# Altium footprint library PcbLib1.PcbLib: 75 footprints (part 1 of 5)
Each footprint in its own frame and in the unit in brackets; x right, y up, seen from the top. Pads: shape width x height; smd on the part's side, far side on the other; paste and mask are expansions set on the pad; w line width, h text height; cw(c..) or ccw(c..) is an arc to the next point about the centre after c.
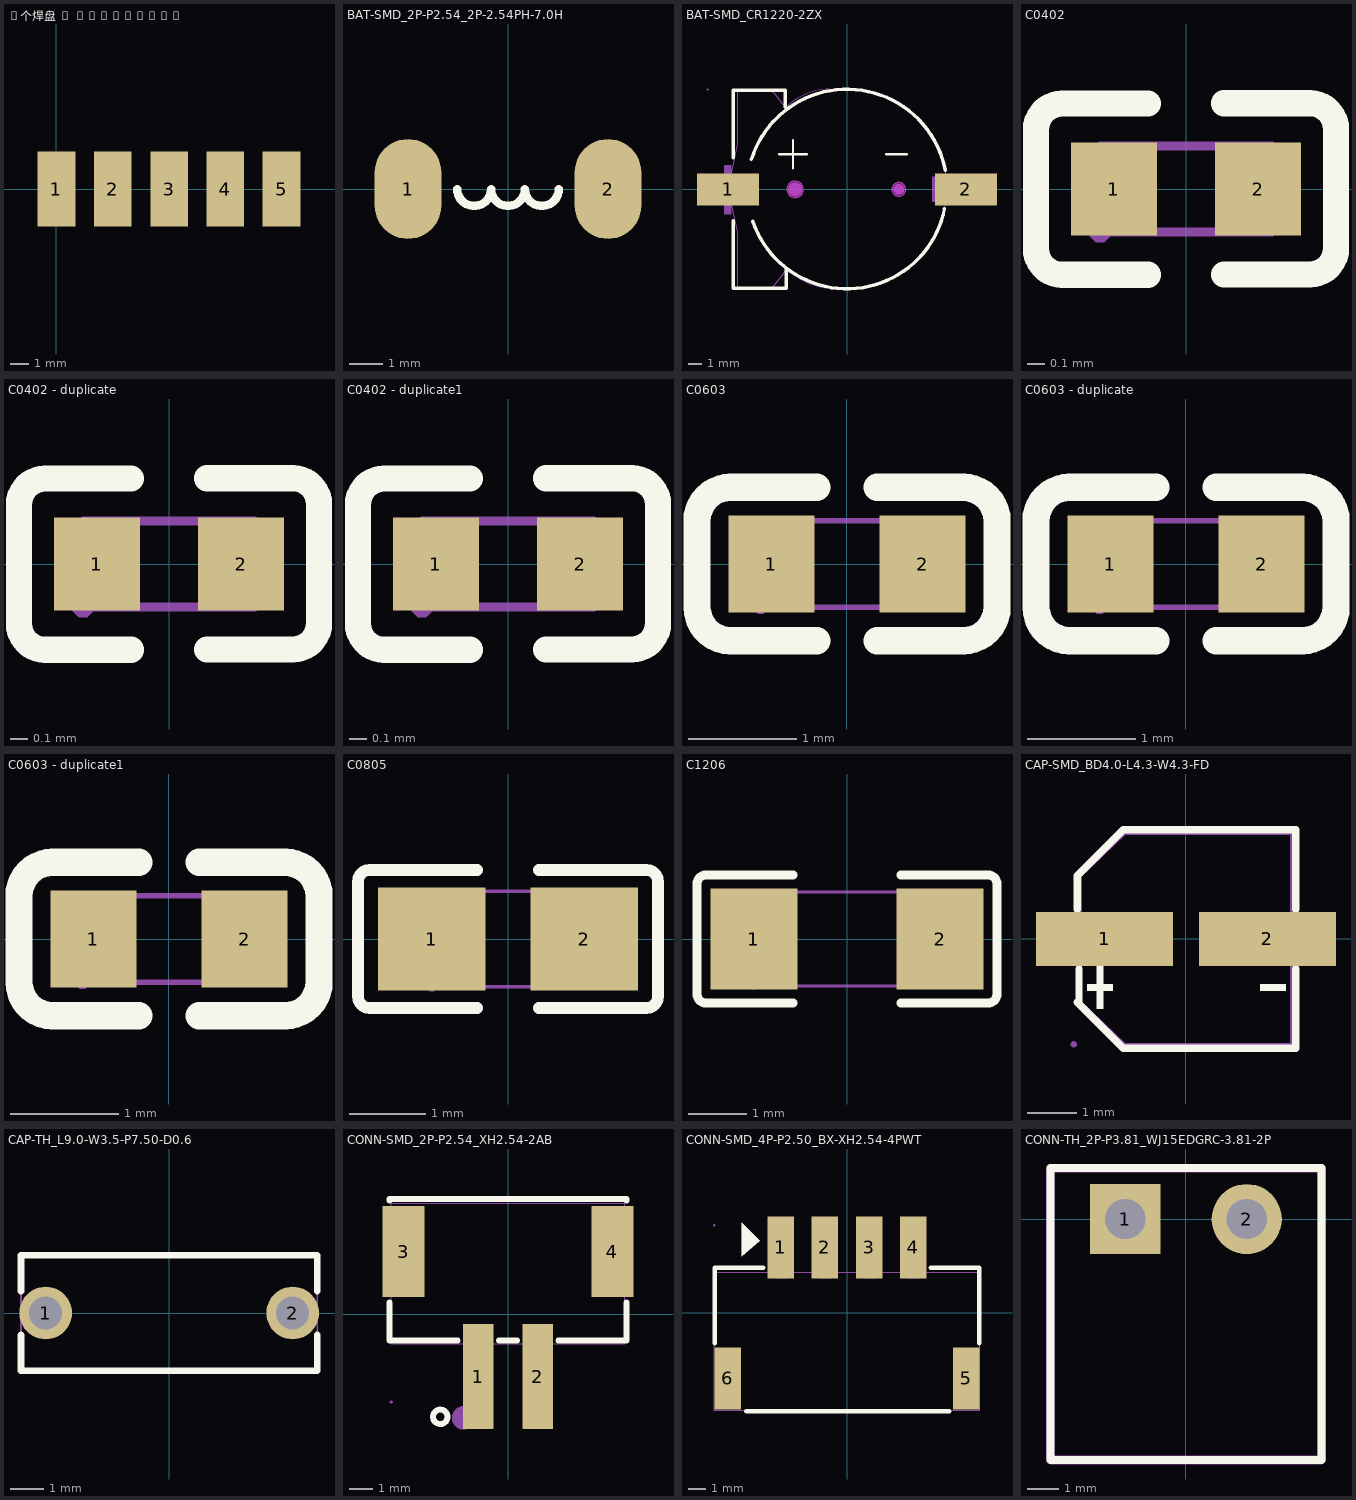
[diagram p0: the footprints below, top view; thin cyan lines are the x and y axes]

## 5个焊盘 - duplicate [mm]
pads (5):
  rect 2x4 smd: 1(0,0) 2(3,0) 3(6.001,0) 4(9,0) 5(12,0)

## BAT-SMD_2P-P2.54_2P-2.54PH-7.0H [mm]
pads (2):
  oval 2x3 smd paste+0 mask+0.05: 1(-3,0) 2(3,0)
Top Overlay:
  lines w0.254: -1.524,0 ccw(c-1.016,0) -0.508,0 ccw(c0,0) 0.508,0 ccw(c1.016,0) 1.524,0

## BAT-SMD_CR1220-2ZX [mm]
pads (2):
  rect 4.5x2.3 smd: 1(-8.6,0) 2(8.6,0)
Top Overlay:
  lines w0.152: -4.928,2.54 -2.896,2.54 ; -3.912,1.524 -3.912,3.556 ; 2.819,2.54 4.343,2.54
  lines w0.254: -8.24,-2.26 -8.24,-7.15 -4.4,-7.15 -4.4,-5.706 -4.378,-5.706 ; -8.24,2.3 -8.24,7.17 -5.51,7.17 -4.47,7.17 -4.47,5.95 ; -6.911,2.175 cw(c0,0) 7.109,1.399 ; -6.815,-2.297 ccw(c0,0) 7.051,-1.418
Keep-Out Layer:
  board cut-out: 4.25,0 4.25,-0.099 4.174,-0.283 4.033,-0.424 3.85,-0.5 3.651,-0.5 3.467,-0.424 3.326,-0.283 3.25,-0.099 3.25,0 3.25,0.099 3.326,0.283 3.467,0.424 3.651,0.5 3.85,0.5 4.033,0.424 4.174,0.283 4.25,0.099 4.25,0
  board cut-out: -3.15,0 -3.15,-0.119 -3.241,-0.34 -3.41,-0.509 -3.631,-0.6 -3.869,-0.6 -4.09,-0.509 -4.259,-0.34 -4.35,-0.119 -4.35,0 -4.35,0.119 -4.259,0.34 -4.09,0.509 -3.869,0.6 -3.631,0.6 -3.41,0.509 -3.241,0.34 -3.15,0.119 -3.15,0
Keep-Out Layer:
  circle w0.003: c3.75,0 r0.5
  circle w0.003: c-3.75,0 r0.6
  region: 4.25,0 4.25,-0.099 4.174,-0.283 4.033,-0.424 3.85,-0.5 3.651,-0.5 3.467,-0.424 3.326,-0.283 3.25,-0.099 3.25,0 3.25,0.099 3.326,0.283 3.467,0.424 3.651,0.5 3.85,0.5 4.033,0.424 4.174,0.283 4.25,0.099 4.25,0
  region: 4.25,0 4.24,-0.098 4.212,-0.191 4.166,-0.278 4.104,-0.354 4.028,-0.416 3.941,-0.462 3.848,-0.49 3.75,-0.5 3.653,-0.49 3.559,-0.462 3.472,-0.416 3.397,-0.354 3.334,-0.278 3.288,-0.191 3.26,-0.098 3.25,0 3.26,0.098 3.288,0.191 3.334,0.278 3.397,0.354 3.472,0.416 3.559,0.462 3.653,0.49 3.75,0.5 3.848,0.49 3.941,0.462 4.028,0.416 4.104,0.354 4.166,0.278 4.212,0.191 4.24,0.098
  region: -3.15,0 -3.15,-0.119 -3.241,-0.34 -3.41,-0.509 -3.631,-0.6 -3.869,-0.6 -4.09,-0.509 -4.259,-0.34 -4.35,-0.119 -4.35,0 -4.35,0.119 -4.259,0.34 -4.09,0.509 -3.869,0.6 -3.631,0.6 -3.41,0.509 -3.241,0.34 -3.15,0.119 -3.15,0
  region: -3.15,0 -3.159,-0.104 -3.186,-0.205 -3.23,-0.3 -3.29,-0.386 -3.364,-0.46 -3.45,-0.52 -3.545,-0.564 -3.646,-0.591 -3.75,-0.6 -3.854,-0.591 -3.955,-0.564 -4.05,-0.52 -4.136,-0.46 -4.21,-0.386 -4.27,-0.3 -4.314,-0.205 -4.341,-0.104 -4.35,0 -4.341,0.104 -4.314,0.205 -4.27,0.3 -4.21,0.386 -4.136,0.46 -4.05,0.52 -3.955,0.564 -3.854,0.591 -3.75,0.6 -3.646,0.591 -3.545,0.564 -3.45,0.52 -3.364,0.46 -3.29,0.386 -3.23,0.3 -3.186,0.205 -3.159,0.104
Mechanical 1:
  circle w0.003: c3.75,0 r0.5
  circle w0.003: c-3.75,0 r0.6
Mechanical 2:
  drawing of 9 lines, arcs and shapes, not listed
Mechanical 6:
  lines w0.051: -8.382,-1.016 -8.382,1.016 -7.89,3.3 -7.89,7.15 -5.47,7.15 -5.2,6.88 -4.47,5.92 -4.43,5.92 cw(c-1.232,2.722) -1.232,7.245 0.081,7.245 cw(c0.081,0.08) 7.245,0.08 7.245,0 cw(c0.053,0) 0.053,-7.192 0,-7.192 -0.843,-7.192 cw(c-0.843,-2.281) -4.315,-5.754 -5.26,-6.93 -5.48,-7.15 -7.89,-7.15 -7.89,-3.3 -8.38,-1.07 -8.382,-1.016
Mechanical 8:
  region: -10.01,7.215 -10.01,7.19 -10.045,7.155 -10.095,7.155 -10.13,7.19 -10.13,7.215 -10.13,7.24 -10.095,7.275 -10.045,7.275 -10.01,7.24 -10.01,7.215
Mechanical 9:
  region: -6.57,-0.9 -10.07,-0.9 -10.07,0.9 -6.57,0.9
  region: 6.17,0.9 9.67,0.9 9.67,-0.9 6.17,-0.9

## C0402 [mm]
pads (2):
  rect 0.5x0.54 smd: 1(-0.42,0) 2(0.42,0)
Top Overlay:
  lines w0.152: -0.221,-0.5 -0.721,-0.5 cw(c-0.721,-0.347) -0.874,-0.347 -0.874,0.345 cw(c-0.721,0.345) -0.721,0.498 -0.221,0.498 ; 0.221,-0.498 0.721,-0.498 ccw(c0.721,-0.345) 0.874,-0.345 0.874,0.347 ccw(c0.721,0.347) 0.721,0.5 0.221,0.5
Mechanical 6:
  lines w0.051: -0.5,-0.25 0.5,-0.25 0.5,0.25 -0.5,0.25 -0.5,-0.25
Mechanical 8:
  region: -0.44,-0.25 -0.44,-0.275 -0.475,-0.31 -0.525,-0.31 -0.56,-0.275 -0.56,-0.25 -0.56,-0.225 -0.525,-0.19 -0.475,-0.19 -0.44,-0.225 -0.44,-0.25
Mechanical 9:
  region: 0.5,-0.25 0.5,0.25 0.25,0.25 0.25,-0.25
  region: -0.5,-0.25 -0.5,0.25 -0.25,0.25 -0.25,-0.25

## C0402 - duplicate [mm]
pads (2):
  rect 0.5x0.54 smd: 1(-0.42,0) 2(0.42,0)
Top Overlay:
  lines w0.152: -0.221,-0.5 -0.721,-0.5 cw(c-0.721,-0.347) -0.874,-0.347 -0.874,0.345 cw(c-0.721,0.345) -0.721,0.498 -0.221,0.498 ; 0.221,-0.498 0.721,-0.498 ccw(c0.721,-0.345) 0.874,-0.345 0.874,0.347 ccw(c0.721,0.347) 0.721,0.5 0.221,0.5
Mechanical 6:
  lines w0.051: -0.5,-0.25 0.5,-0.25 0.5,0.25 -0.5,0.25 -0.5,-0.25
Mechanical 8:
  region: -0.44,-0.25 -0.44,-0.275 -0.475,-0.31 -0.525,-0.31 -0.56,-0.275 -0.56,-0.25 -0.56,-0.225 -0.525,-0.19 -0.475,-0.19 -0.44,-0.225 -0.44,-0.25
Mechanical 9:
  region: 0.5,-0.25 0.5,0.25 0.25,0.25 0.25,-0.25
  region: -0.5,-0.25 -0.5,0.25 -0.25,0.25 -0.25,-0.25

## C0402 - duplicate1 [mm]
pads (2):
  rect 0.5x0.54 smd: 1(-0.42,0) 2(0.42,0)
Top Overlay:
  lines w0.152: -0.221,-0.5 -0.721,-0.5 cw(c-0.721,-0.347) -0.874,-0.347 -0.874,0.345 cw(c-0.721,0.345) -0.721,0.498 -0.221,0.498 ; 0.221,-0.498 0.721,-0.498 ccw(c0.721,-0.345) 0.874,-0.345 0.874,0.347 ccw(c0.721,0.347) 0.721,0.5 0.221,0.5
Mechanical 6:
  lines w0.051: -0.5,-0.25 0.5,-0.25 0.5,0.25 -0.5,0.25 -0.5,-0.25
Mechanical 8:
  region: -0.44,-0.25 -0.44,-0.275 -0.475,-0.31 -0.525,-0.31 -0.56,-0.275 -0.56,-0.25 -0.56,-0.225 -0.525,-0.19 -0.475,-0.19 -0.44,-0.225 -0.44,-0.25
Mechanical 9:
  region: 0.5,-0.25 0.5,0.25 0.25,0.25 0.25,-0.25
  region: -0.5,-0.25 -0.5,0.25 -0.25,0.25 -0.25,-0.25

## C0603 [mm]
pads (2):
  rect 0.8x0.9 smd: 1(-0.7,0) 2(0.7,0)
Top Overlay:
  lines w0.254: -1.08,-0.71 -0.28,-0.71 ; -1.08,0.71 -0.28,0.71 ; -1.08,-0.71 cw(c-1.08,-0.4) -1.39,-0.4 -1.39,0.4 cw(c-1.08,0.4) -1.08,0.71 ; 0.28,-0.71 1.08,-0.71 ccw(c1.08,-0.4) 1.39,-0.4 1.39,0.4 ccw(c1.08,0.4) 1.08,0.71 0.28,0.71
Mechanical 6:
  lines w0.051: -0.8,-0.4 -0.8,0.4 0.8,0.4 0.8,-0.4 -0.8,-0.4
Mechanical 8:
  region: -0.74,-0.4 -0.74,-0.425 -0.775,-0.46 -0.825,-0.46 -0.86,-0.425 -0.86,-0.4 -0.86,-0.375 -0.825,-0.34 -0.775,-0.34 -0.74,-0.375 -0.74,-0.4
Mechanical 9:
  region: -0.8,-0.4 -0.8,0.4 -0.5,0.4 -0.5,-0.4
  region: 0.8,-0.4 0.8,0.4 0.5,0.4 0.5,-0.4

## C0603 - duplicate [mm]
pads (2):
  rect 0.8x0.9 smd: 1(-0.7,0) 2(0.7,0)
Top Overlay:
  lines w0.254: -1.08,-0.71 -0.28,-0.71 ; -1.08,0.71 -0.28,0.71 ; -1.08,-0.71 cw(c-1.08,-0.4) -1.39,-0.4 -1.39,0.4 cw(c-1.08,0.4) -1.08,0.71 ; 0.28,-0.71 1.08,-0.71 ccw(c1.08,-0.4) 1.39,-0.4 1.39,0.4 ccw(c1.08,0.4) 1.08,0.71 0.28,0.71
Mechanical 6:
  lines w0.051: -0.8,-0.4 0.8,-0.4 0.8,0.4 -0.8,0.4 -0.8,-0.4
Mechanical 8:
  region: -0.74,-0.4 -0.74,-0.425 -0.775,-0.46 -0.825,-0.46 -0.86,-0.425 -0.86,-0.4 -0.86,-0.375 -0.825,-0.34 -0.775,-0.34 -0.74,-0.375 -0.74,-0.4
Mechanical 9:
  region: 0.8,-0.4 0.8,0.4 0.5,0.4 0.5,-0.4
  region: -0.8,-0.4 -0.8,0.4 -0.5,0.4 -0.5,-0.4

## C0603 - duplicate1 [mm]
pads (2):
  rect 0.8x0.9 smd: 1(-0.7,0) 2(0.7,0)
Top Overlay:
  lines w0.254: -1.08,-0.71 -0.28,-0.71 ; -1.08,0.71 -0.28,0.71 ; -1.08,-0.71 cw(c-1.08,-0.4) -1.39,-0.4 -1.39,0.4 cw(c-1.08,0.4) -1.08,0.71 ; 0.28,-0.71 1.08,-0.71 ccw(c1.08,-0.4) 1.39,-0.4 1.39,0.4 ccw(c1.08,0.4) 1.08,0.71 0.28,0.71
Mechanical 6:
  lines w0.051: -0.8,-0.4 0.8,-0.4 0.8,0.4 -0.8,0.4 -0.8,-0.4
Mechanical 8:
  region: -0.74,-0.4 -0.74,-0.425 -0.775,-0.46 -0.825,-0.46 -0.86,-0.425 -0.86,-0.4 -0.86,-0.375 -0.825,-0.34 -0.775,-0.34 -0.74,-0.375 -0.74,-0.4
Mechanical 9:
  region: 0.8,-0.4 0.8,0.4 0.5,0.4 0.5,-0.4
  region: -0.8,-0.4 -0.8,0.4 -0.5,0.4 -0.5,-0.4

## C0805 [mm]
pads (2):
  rect 1.41x1.35 smd paste-100 mask+0.051: 1(-1,0) 2(1,0)
Top Overlay:
  lines w0.152: -0.401,-0.904 -1.811,-0.904 cw(c-1.811,-0.751) -1.964,-0.751 -1.964,0.751 cw(c-1.811,0.751) -1.811,0.904 -0.401,0.904 ; 0.401,-0.904 1.811,-0.904 ccw(c1.811,-0.751) 1.964,-0.751 1.964,0.751 ccw(c1.811,0.751) 1.811,0.904 0.401,0.904
Top Paste:
  region: 1.705,0.64 1.705,-0.64 1.655,-0.69 0.505,-0.69 0.455,-0.64 0.45,-0.23 0.9,-0.23 0.9,0.22 0.46,0.22 0.455,0.64 0.505,0.69 1.655,0.69
  region: -1.705,-0.64 -1.705,0.64 -1.655,0.69 -0.505,0.69 -0.455,0.64 -0.45,0.23 -0.9,0.23 -0.9,-0.22 -0.46,-0.22 -0.455,-0.64 -0.505,-0.69 -1.655,-0.69
Mechanical 6:
  lines w0.051: -1,-0.625 1,-0.625 1,0.625 -1,0.625 -1,-0.625
Mechanical 8:
  region: -0.94,-0.625 -0.94,-0.65 -0.975,-0.685 -1.025,-0.685 -1.06,-0.65 -1.06,-0.625 -1.06,-0.6 -1.025,-0.565 -0.975,-0.565 -0.94,-0.6 -0.94,-0.625
Mechanical 9:
  region: 1,0.625 1,-0.625 0.5,-0.625 0.5,0.625
  region: -1,-0.625 -1,0.625 -0.5,0.625 -0.5,-0.625

## C1206 [mm]
pads (2):
  rect 1.485x1.728 smd paste-100 mask+0.051: 1(-1.593,0) 2(1.593,0)
Top Overlay:
  lines w0.152: -0.926,-1.093 -2.411,-1.093 cw(c-2.411,-0.94) -2.564,-0.94 -2.564,0.94 cw(c-2.411,0.94) -2.411,1.093 -0.926,1.093 ; 0.926,-1.093 2.411,-1.093 ccw(c2.411,-0.94) 2.564,-0.94 2.564,0.94 ccw(c2.411,0.94) 2.411,1.093 0.926,1.093
Top Paste:
  region: 0.85,-0.764 0.85,-0.394 0.95,-0.294 1.255,-0.294 1.355,-0.194 1.355,0.194 1.255,0.294 0.95,0.294 0.85,0.394 0.85,0.764 0.95,0.864 2.235,0.864 2.335,0.764 2.335,-0.764 2.235,-0.864 0.95,-0.864
  region: -0.85,-0.764 -0.85,-0.394 -0.95,-0.294 -1.255,-0.294 -1.355,-0.194 -1.355,0.194 -1.255,0.294 -0.95,0.294 -0.85,0.394 -0.85,0.764 -0.95,0.864 -2.235,0.864 -2.335,0.764 -2.335,-0.764 -2.235,-0.864 -0.95,-0.864
Mechanical 6:
  lines w0.051: -1.6,-0.8 -1.6,0.8 1.6,0.8 1.6,-0.8 -1.6,-0.8
Mechanical 8:
  region: -1.54,-0.8 -1.54,-0.825 -1.575,-0.86 -1.625,-0.86 -1.66,-0.825 -1.66,-0.8 -1.66,-0.775 -1.625,-0.74 -1.575,-0.74 -1.54,-0.775 -1.54,-0.8
Mechanical 9:
  region: -1.6,-0.8 -1.6,0.8 -1.1,0.8 -1.1,-0.8
  region: 1.6,-0.8 1.6,0.8 1.1,0.8 1.1,-0.8

## CAP-SMD_BD4.0-L4.3-W4.3-FD [mm]
pads (2):
  rect 2.8x1.1 smd: 1(-1.661,0) 2(1.661,0)
Top Overlay:
  region: 2.031,-0.925 2.031,-1.054 1.515,-1.054 1.515,-0.925
  region: -2.011,-0.925 -2.011,-1.054 -1.495,-1.054 -1.495,-0.925
  region: -1.818,-0.559 -1.818,-1.419 -1.689,-1.419 -1.689,-0.559
  lines w0.152: -2.217,-1.29 -1.28,-2.226 2.236,-2.226 2.236,-0.607 ; -2.217,0.607 -2.217,1.29 -1.28,2.226 2.236,2.226 2.236,0.607 ; -2.183,-1.29 -2.183,-0.607
Mechanical 2:
  region: 2.031,0.064 2.031,-0.065 1.515,-0.065 1.515,0.064
  region: -2.011,0.064 -2.011,-0.065 -1.495,-0.065 -1.495,0.064
  region: -1.818,0.43 -1.818,-0.43 -1.689,-0.43 -1.689,0.43
Mechanical 6:
  lines w0.051: -2.15,-1.281 -1.248,-2.15 2.15,-2.15 2.15,2.15 -1.248,2.15 -2.15,1.281 -2.15,-1.281
Mechanical 8:
  region: -2.23,-2.15 -2.23,-2.175 -2.266,-2.21 -2.315,-2.21 -2.35,-2.175 -2.35,-2.15 -2.35,-2.125 -2.315,-2.09 -2.266,-2.09 -2.23,-2.125 -2.23,-2.15
Mechanical 9:
  region: 2.31,0.325 2.31,-0.325 0.51,-0.325 0.51,0.325
  region: -2.29,0.325 -2.29,-0.325 -0.49,-0.325 -0.49,0.325

## CAP-TH_L9.0-W3.5-P7.50-D0.6 [mm]
pads (2):
  round 1.6 hole 1: 1(-3.75,0) 2(3.75,0)
Top Overlay:
  lines w0.2: -4.5,-0.666 -4.5,-1.75 4.5,-1.75 4.5,-0.666 ; -4.5,0.666 -4.5,1.75 4.5,1.75 4.5,0.666
Mechanical 6:
  lines w0.051: -4.5,-1.75 -4.5,1.75 4.5,1.75 4.5,-1.75 -4.5,-1.75
Mechanical 8:
  region: -4.44,-1.75 -4.44,-1.775 -4.475,-1.81 -4.525,-1.81 -4.56,-1.775 -4.56,-1.75 -4.56,-1.725 -4.525,-1.69 -4.475,-1.69 -4.44,-1.725 -4.44,-1.75
Mechanical 9:
  region: -3.45,0 -3.45,-0.06 -3.496,-0.17 -3.58,-0.254 -3.69,-0.3 -3.81,-0.3 -3.92,-0.254 -4.004,-0.17 -4.05,-0.06 -4.05,0 -4.05,0.06 -4.004,0.17 -3.92,0.254 -3.81,0.3 -3.69,0.3 -3.58,0.254 -3.496,0.17 -3.45,0.06 -3.45,0
  region: 4.05,0 4.05,-0.06 4.004,-0.17 3.92,-0.254 3.81,-0.3 3.69,-0.3 3.58,-0.254 3.496,-0.17 3.45,-0.06 3.45,0 3.45,0.06 3.496,0.17 3.58,0.254 3.69,0.3 3.81,0.3 3.92,0.254 4.004,0.17 4.05,0.06 4.05,0

## CONN-SMD_2P-P2.54_XH2.54-2AB [mm]
pads (4):
  rect 1.3x4.5 smd: 1(-1.269,-2.675) 2(1.27,-2.675)
  rect 1.8x3.9 smd: 3(-4.47,2.675) 4(4.47,2.675)
Top Overlay:
  circle w0.254: c-2.9,-4.4 r0.31
  lines w0.254: -5.078,0.493 -5.078,-1.135 -2.151,-1.135 ; -5.078,4.857 -5.078,4.925 5.08,4.925 5.08,4.857 ; -0.388,-1.135 0.389,-1.135 ; 2.152,-1.135 5.08,-1.135 5.08,0.493
Mechanical 2:
  circle w0.5: c-1.905,-4.445 r0.25
Mechanical 6:
  lines w0.051: -5,-1.27 5,-1.27 5,4.73 -5,4.73 -5,-1.27
Mechanical 8:
  region: -4.94,-3.77 -4.94,-3.795 -4.975,-3.83 -5.025,-3.83 -5.06,-3.795 -5.06,-3.77 -5.06,-3.745 -5.025,-3.71 -4.975,-3.71 -4.94,-3.745 -4.94,-3.77
Mechanical 9:
  region: -4.72,3.925 -4.22,3.925 -4.22,1.425 -4.72,1.425
  region: 4.22,3.925 4.72,3.925 4.72,1.425 4.22,1.425
  region: 0.95,-1.22 1.59,-1.22 1.59,-3.77 0.95,-3.77
  region: -1.589,-1.22 -0.949,-1.22 -0.949,-3.77 -1.589,-3.77

## CONN-SMD_4P-P2.50_BX-XH2.54-4PWT [mm]
pads (6):
  rect 1.5x3.5 smd paste+0 mask+0.05: 1(-3.75,3.7) 2(-1.25,3.7) 3(1.25,3.7) 4(3.75,3.7) 5(6.73,-3.7) 6(-6.73,-3.7)
Top Overlay:
  region: -4.946,4.081 -5.962,5.097 -5.962,3.192
  lines w0.254: -7.486,-1.719 -7.486,2.557 -4.731,2.557 ; -5.708,-5.571 5.783,-5.571 ; 4.73,2.558 6.389,2.558 7.486,2.558 7.486,-1.719
Mechanical 2:
  region: -4.946,4.081 -5.962,5.097 -5.962,3.192
Mechanical 6:
  lines w0.051: -7.5,-5.502 -7.5,2.298 7.5,2.298 7.5,-5.502 -7.5,-5.502
Mechanical 8:
  region: -7.44,4.95 -7.44,4.925 -7.475,4.89 -7.525,4.89 -7.56,4.925 -7.56,4.95 -7.56,4.975 -7.525,5.01 -7.475,5.01 -7.44,4.975 -7.44,4.95
Mechanical 9:
  region: -4.07,4.95 -3.43,4.95 -3.43,1.95 -4.07,1.95
  region: -1.57,4.95 -0.93,4.95 -0.93,1.95 -1.57,1.95
  region: 0.93,4.95 1.57,4.95 1.57,1.95 0.93,1.95
  region: 3.43,4.95 4.07,4.95 4.07,1.95 3.43,1.95
  region: -6.93,-2.45 -6.53,-2.45 -6.53,-4.95 -6.93,-4.95
  region: 6.53,-2.45 6.93,-2.45 6.93,-4.95 6.53,-4.95

## CONN-TH_2P-P3.81_WJ15EDGRC-3.81-2P [mm]
pads (2):
  rect 2.2x2.2 hole 1.26: 1(-1.905,0)
  round 2.2 hole 1.26: 2(1.905,0)
Top Overlay:
  lines w0.254: -4.25,-7.55 -4.25,1.6 4.25,1.6 4.25,-7.55 -4.25,-7.55
Mechanical 2:
  region: -4.123,1.6 -4.123,-7.423 4.123,-7.423 4.123,1.6 4.133,1.649 4.16,1.69 4.201,1.717 4.25,1.727 4.299,1.717 4.34,1.69 4.367,1.649 4.377,1.6 4.377,-7.55 4.367,-7.599 4.34,-7.64 4.299,-7.667 4.25,-7.677 -4.25,-7.677 -4.299,-7.667 -4.34,-7.64 -4.367,-7.599 -4.377,-7.55 -4.377,1.6 -4.367,1.649 -4.34,1.69 -4.299,1.717 -4.25,1.727 -4.201,1.717 -4.16,1.69 -4.133,1.649
  region: 4.25,1.473 -4.25,1.473 -4.299,1.483 -4.34,1.51 -4.367,1.551 -4.377,1.6 -4.367,1.649 -4.34,1.69 -4.299,1.717 -4.25,1.727 4.25,1.727 4.299,1.717 4.34,1.69 4.367,1.649 4.377,1.6 4.367,1.551 4.34,1.51 4.299,1.483
Mechanical 6:
  lines w0.051: -4.25,-7.55 -4.25,1.6 4.25,1.6 4.25,-7.55 -4.25,-7.55
Mechanical 8:
  region: -4.19,-7.55 -4.19,-7.575 -4.225,-7.61 -4.275,-7.61 -4.31,-7.575 -4.31,-7.55 -4.31,-7.525 -4.275,-7.49 -4.225,-7.49 -4.19,-7.525 -4.19,-7.55
Mechanical 9:
  region: 1.505,0.4 2.305,0.4 2.305,-0.4 1.505,-0.4
  region: -2.305,0.4 -1.505,0.4 -1.505,-0.4 -2.305,-0.4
